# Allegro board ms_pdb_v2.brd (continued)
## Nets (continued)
UART_CTS_P1_L_N: J19.8(LAN8) J26.B65(GND27)
UART_CTS_P2_L_N: J21.8(LAN8) J26.A65(HSIP11-)
UART_CTS_P5_L_N: J23.8(LAN8) J26.B57(GND23)
UART_CTS_P6_L_N: J26.A57(HSIP9-) J27.8(LAN8)
UART_DSR_P1_L_N: J19.2(LAN2) J26.B61(GND25)
UART_DSR_P2_L_N: J21.2(LAN2) J26.A61(HSIP10-)
UART_DSR_P5_L_N: J23.2(LAN2) J26.B53(GND21)
UART_DSR_P6_L_N: J26.A53(HSIP8-) J27.2(LAN2)
UART_DTR_P1_L_N: J19.7(LAN7) J26.B64(GND26)
UART_DTR_P2_L_N: J21.7(LAN7) J26.A64(HSIP11+)
UART_DTR_P5_L_N: J23.7(LAN7) J26.B56(GND22)
UART_DTR_P6_L_N: J26.A56(HSIP9+) J27.7(LAN7)
UART_RI_P5_L_N: J23.4(LAN4) J26.B58(HSOP10+)
UART_RI_P6_L_N: J26.A58(GND56) J27.4(LAN4)
UART_RTS_P1_L_N: J19.1(LAN1) J26.B60(GND24)
UART_RTS_P2_L_N: J21.1(LAN1) J26.A60(HSIP10+)
UART_RTS_P5_L_N: J23.1(LAN1) J26.B52(GND20)
UART_RTS_P6_L_N: J26.A52(HSIP8+) J27.1(LAN1)
UART_RX_P1_L: J19.3(LAN3) J26.B62(HSOP11+)
UART_RX_P2_L: J21.3(LAN3) J26.A62(GND58)
UART_RX_P5_L: J23.3(LAN3) J26.B54(HSOP9+)
UART_RX_P6_L: J26.A54(GND54) J27.3(LAN3)
UART_TX_P1_L: J19.6(LAN6) J26.B63(HSOP11-)
UART_TX_P2_L: J21.6(LAN6) J26.A63(GND59)
UART_TX_P5_L: J23.6(LAN6) J26.B55(HSOP9-)
UART_TX_P6_L: J26.A55(GND55) J27.6(LAN6)
N42126673: J29.10(D2) R148.1
N42126764: J29.9(D1) R149.1
N42130542: J29.12(D4) R150.2
N42132358: J28.12(D4) R153.2
N42132545: J28.10(D2) R151.1
N42132933: J28.9(D1) R152.1
N42241895: R154.2 U2.1(EN)
N42242090: R156.2 R157.1 U2.4(ADJ)
N42242336: C88.1 R155.2
N42263600: C92.1 R158.2 R159.1 R161.1 U3.1(C)
N42264085: R159.2 R160.1 U3.8(REF)

Pads without a net: J1 34; J2 34; J3 34; J4 34; J5 34; J6 34; J25 A13 A14 A16 A19 A21 A22 B14 B15 B17 B19 B20 B23 B24; J26 A67 A68 A69 B67 B70; J28 11; J29 11; NOREF#21 1; NOREF#35 1; NOREF#102 1; NOREF#108 1; NOREF#109 1; NOREF#110 1; U3 4 5

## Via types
v1: diameter 0.762, hole 0.381, TOP to BOTTOM, 31 vias
v2: diameter 0.508, hole 0.254, TOP to BOTTOM, 1901 vias
v3: diameter 0.66, hole 0.33, TOP to BOTTOM, 24 vias

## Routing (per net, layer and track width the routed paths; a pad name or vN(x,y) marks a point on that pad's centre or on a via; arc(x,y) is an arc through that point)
GND: length 352.2
  TOP w0.457: R7.2 v2(25.91,108.23) ; R50.1 v2(27.45,9.88) ; R39.1 v2(13.85,329.31) ; R65.2 R45.2 26.88,5.61 v2(27.01,5.74) ; R6.2 v2(25.72,196.62) ; v2(26.07,12.56) 26.65,11.98 R49.1 ; v2(68.6,206.3) 68.59,206.29 R120.2 ; R53.1 v2(24.76,367.77) ; R38.1 v2(16.02,329.26) ; R140.2 v2(14.59,318.36) ; R54.1 v2(25.22,454.65) ; R22.2 v2(26.84,461.07) ; R52.1 v2(25.06,278.49) ; R37.1 v2(17.16,329.35) ; R116.2 v2(69.85,117.63) ; R51.1 v2(24.92,189.27) ; R112.2 v2(67.98,29.35)
  TOP w0.508: C8.2 v2(68.97,66.13) ; C80.2 v2(82.5,509.34) ; C41.2 v2(68.25,215.26) ; C2.2 v2(76.12,20.01) ; R160.2 v2(22.52,178.84) ; C54.2 v2(69.11,302.71) ; C74.2 v2(73.53,437.83) ; C75.2 v2(72.28,437.76) ; R24.2 41.43,370.1 v2(41.43,370.1) ; R43.2 v2(24.74,8.34) ; C53.2 v2(70.31,302.71) ; v2(20.2,173.34) 19.76,172.9 U3.3 ; C56.2 v2(66.69,302.71) ; C73.2 v2(74.05,464.78) ; C47.2 v2(73.69,258.11) ; C17.2 v2(73.91,109.94) ; U3.2 v2(20.2,174.17) ; C9.2 v2(70.26,65.13) ; R69.2 v2(24.75,94.46) ; C26.2 v2(69.44,126.32) ; C27.2 v2(68.31,126.32) ; R124.2 v2(82.75,295.22) ; C33.2 v2(70.85,170.74) ; C10.2 v2(71.42,65.18) ; C44.2 v2(73.2,287.31) ; R63.2 v2(24.74,9.51) ; C62.2 v2(69.86,349.18) ; C46.2 v2(74.83,258.11) ; R71.2 v2(24.75,187.95) ; R27.2 v2(41.28,371.51) ; R47.2 v2(24.77,95.65) ; R48.2 v2(24.77,186.75) ; v2(41.47,461.17) 41.47,461.18 R23.2 ; R99.2 v2(46.83,254.4) ; C91.2 v2(22.56,449.86) ; C76.2 v2(71.04,437.74) ; v2(40.99,103.52) R11.2 ; C84.2 v2(69.55,482.18) ; C64.2 v2(72.16,421.61) ; R20.2 v2(26.84,285.98) ; R25.2 v2(41.18,281.14) ; C42.2 v2(67.1,215.23) ; C29.2 v2(69.37,199.64) ; C5.2 v2(79.52,20.01) ; R12.2 v2(41.3,17.31) ; U1.4 v2(13.75,333.7) ; C63.2 v2(68.73,349.16) ; C61.2 v2(71,349.13) ; C32.2 v2(71.97,170.74) ; C51.2 v2(73.46,331.63) ; C66.2 v2(74.7,420.77) ; C1.2 v2(74.8,21.01) ; R85.2 v2(25.17,448.49) ; C40.2 v2(69.42,215.2) ; C50.2 v2(72.09,332.48) ; R95.2 v2(46.9,249.79) ; R132.2 v2(74.58,472.1) ; U2.8 v2(17.88,456.28) ; R58.2 v2(24.64,366.71) ; C57.2 v2(68.64,376.62) ; R44.1 40.79,374.15 v2(41.21,373.73) ; R91.2 v2(46.79,245.71) ; R77.2 v2(24.61,271.15) ; C78.2 v2(79.9,510.31) ; C65.2 v2(73.51,420.77) ; C55.2 v2(67.87,302.71) ; R151.2 v2(2.83,416.16) ; U2.6 v2(20.42,456.23) ; C16.2 v2(72.81,109.94) ; C14.2 v2(66.82,37.51) ; C86.2 v2(13.99,447.8) ; C69.2 v2(75.1,391.98) ; C13.2 v2(67.92,37.48) ; C35.2 v2(68.61,170.74) ; C60.2 v2(72.2,349.13) ; R107.2 v2(46.77,258.9) ; C34.2 v2(69.73,170.74) ; C23.2 v2(73.91,154.23) ; C37.2 v2(73.96,242.94) ; C22.2 v2(72.48,155.08) ; C49.2 v2(71.41,258.11) ; R89.2 v2(46.81,240.88) ; C36.2 v2(72.64,243.78) ; R59.2 v2(24.85,360.55) ; C6.2 v2(80.66,20.01) ; R57.2 v2(24.58,272.35) ; U3.6 v2(21.89,172.9) ; v2(40.96,106.9) R8.2 ; R152.2 v2(4.2,416.05) ; C83.2 v2(70.68,482.18) ; C58.2 v2(69.98,375.78) ; C4.2 v2(78.4,20.01) ; C92.2 v2(20.72,179.18) ; C38.2 v2(75.15,242.94) ; R150.1 v2(3.41,125.97) ; R148.2 v2(2.77,147.03) ; C70.2 v2(73.93,391.98) ; R19.2 26.79,373.45 v2(26.79,374.12) ; C82.2 v2(71.81,482.18) ; v2(26.45,20.97) 26.45,19.86 R5.2 ; C7.2 v2(81.79,20.01) ; C68.2 v2(76.3,391.98) ; R42.1 40.47,197.27 v2(40.93,196.82) ; R55.2 v2(25.04,183.07) ; R61.2 v2(25.16,447.25) ; R128.2 v2(79.73,384.53) ; C59.2 v2(71.12,375.78) ; R46.2 v2(24.89,99.37) ; R60.2 v2(25.16,453.54) ; v2(41.18,459.17) R26.2 ; C87.2 v2(14.11,449.79) ; C88.2 v2(23.82,444.05) ; C15.2 v2(71.52,110.79) ; R73.2 v2(25.04,181.85) ; R81.2 v2(24.74,361.78) ; C12.2 v2(69.07,37.5) ; C18.2 v2(74.8,81.96) ; C48.2 v2(72.56,258.11) ; v2(23.23,448.33) 23.07,448.33 22.85,448.1 C89.2 22.11,447.41 22.51,447.01 R157.2 ; R153.1 v2(2.93,396.83) ; v2(41.79,283.5) R21.2 ; C20.2 v2(72.52,81.96) ; R79.2 v2(24.64,365.5) ; C71.2 v2(71.39,465.98) ; U3.7 v2(22.01,174.17) ; C30.2 v2(70.66,198.79) ; C67.2 v2(77.44,391.98) ; R103.2 46.78,260.36 v2(47.85,259.29) ; C19.2 v2(73.63,81.96) ; C24.2 v2(75.06,154.23) ; U2.5 v2(21.69,456.24) ; R67.2 v2(24.8,100.59) ; C45.2 v2(74.35,287.31) ; C11.2 v2(70.24,37.49) ; U2.7 v2(19.15,456.24) ; v2(41.25,14.41) R9.2 ; C81.2 v2(72.93,482.18) ; R40.1 v2(41.08,18.41) ; C31.2 v2(71.82,198.79) ; C28.2 v2(67.19,126.32) ; C72.2 v2(72.8,464.67) ; R75.2 v2(24.63,276.12) ; C77.2 v2(69.77,437.69) ; R13.2 v2(41.06,194.11) ; C85.2 v2(13.96,445.81) ; R56.2 v2(24.62,277.38) ; C43.2 v2(71.87,288.16) ; R149.2 v2(4.06,147.03) ; C25.2 v2(70.56,126.32) ; v2(41.1,192.22) R10.2 ; C3.2 v2(77.25,20.01) ; C39.2 v2(70.56,215.2) ; C52.2 v2(74.71,331.63) ; C79.2 v2(81.29,509.32) ; C21.2 v2(71.39,81.96) ; C90.2 v2(14.33,451.71) ; R83.2 v2(25.11,452.26)
  IN2 w0.635: CE1.2 49.15,18.57 ; CE1.2 48.2,17.62 ; CE1.2 47.25,18.57 ; CE1.2 48.2,19.52 ; 47.25,107.12 CE5.2 ; CE5.2 48.2,108.07 ; CE5.2 48.2,106.17 ; CE5.2 49.15,107.12 ; 48.8,417.68 CE19.2 ; CE19.2 49.76,418.64 ; CE19.2 48.8,419.59 ; CE19.2 47.85,418.64 ; CE13.2 48.58,286.16 ; CE13.2 48.58,284.25 ; CE13.2 49.53,285.21 ; CE13.2 47.62,285.21 ; 47.7,463.1 CE22.2 ; CE22.2 49.6,463.1 ; CE22.2 48.65,462.15 ; CE22.2 48.65,464.05 ; 48.47,172.18 CE9.2 ; CE9.2 48.47,174.09 ; CE9.2 47.51,173.14 ; CE9.2 49.42,173.14 ; 47.17,374.44 CE17.2 ; CE17.2 48.12,373.48 ; CE17.2 48.12,375.39 ; CE17.2 49.08,374.44 ; CE16.2 48.4,351.72 ; CE16.2 48.4,349.81 ; CE16.2 47.45,350.77 ; CE16.2 49.35,350.77 ; 47.85,507.68 CE23.2 ; CE23.2 48.8,508.63 ; CE23.2 49.75,507.68 ; CE23.2 48.8,506.72 ; CE10.2 48.73,197.68 ; CE10.2 48.73,195.78 ; CE10.2 49.68,196.73 ; CE10.2 47.78,196.73 ; CE3.2 48.35,63.84 ; CE3.2 49.3,62.88 ; CE3.2 47.4,62.88 ; CE3.2 48.35,61.93 ; 48.67,216.53 CE11.2 ; CE11.2 47.71,217.49 ; CE11.2 48.67,218.44 ; CE11.2 49.62,217.49 ; CE2.2 49.29,38.62 ; CE2.2 48.33,39.57 ; CE2.2 47.38,38.62 ; CE2.2 48.33,37.67 ; CE4.2 49.42,84.27 ; CE4.2 47.51,84.27 ; CE4.2 48.47,85.23 ; CE4.2 48.47,83.32 ; CE20.2 49.62,439.76 ; CE20.2 48.67,440.72 ; CE20.2 48.67,438.81 ; CE20.2 47.72,439.76 ; 48.4,127.7 CE6.2 ; CE6.2 49.35,128.66 ; CE6.2 47.45,128.66 ; CE6.2 48.4,129.61 ; CE15.2 49.68,329.97 ; CE15.2 48.73,330.93 ; CE15.2 48.73,329.02 ; CE15.2 47.78,329.97 ; CE14.2 48.6,307.34 ; CE14.2 47.65,306.38 ; CE14.2 49.55,306.38 ; CE14.2 48.6,305.43 ; CE24.2 49.6,519.02 ; CE24.2 47.7,519.02 ; CE24.2 48.65,519.97 ; CE24.2 48.65,518.07 ; 48.53,394.6 CE18.2 ; CE18.2 48.53,396.5 ; CE18.2 49.49,395.55 ; CE18.2 47.58,395.55 ; 48.33,481.75 CE21.2 ; CE21.2 47.38,482.71 ; CE21.2 48.33,483.66 ; CE21.2 49.29,482.71 ; CE12.2 49.86,241.54 ; CE12.2 50.82,240.59 ; CE12.2 48.91,240.59 ; CE12.2 49.86,239.64 ; 48.04,151.93 CE8.2 ; CE8.2 49.95,151.93 ; CE8.2 48.99,152.88 ; CE8.2 48.99,150.97
  BOTTOM w0.356: v2(89.49,479.37) 89.4,479.28 U7.7 ; v2(94.89,343.55) 94.52,343.18 U6.7 ; v2(91.9,79.23) 91.36,78.69 U4.7 ; U5.7 v2(89.92,165.65)
  BOTTOM w0.66: 48.65,518.07 CE24.2 ; CE24.2 48.65,519.97 ; CE24.2 47.7,519.02 ; CE24.2 49.6,519.02 ; 48.47,83.32 CE4.2 ; CE4.2 48.47,85.23 ; CE4.2 49.42,84.27 ; CE4.2 47.51,84.27 ; 48.33,481.75 CE21.2 ; CE21.2 47.38,482.71 ; CE21.2 48.33,483.66 ; CE21.2 49.29,482.71 ; 48.65,462.15 CE22.2 ; CE22.2 48.65,464.05 ; CE22.2 49.6,463.1 ; CE22.2 47.7,463.1 ; CE5.2 48.2,108.07 ; CE5.2 48.2,106.17 ; CE5.2 49.15,107.12 ; CE5.2 47.25,107.12 ; 48.2,17.62 CE1.2 ; CE1.2 47.25,18.57 ; CE1.2 48.2,19.52 ; CE1.2 49.15,18.57 ; 48.91,240.59 CE12.2 ; CE12.2 50.82,240.59 ; CE12.2 49.86,241.54 ; CE12.2 49.86,239.64 ; CE18.2 49.49,395.55 ; CE18.2 48.53,394.6 ; CE18.2 48.53,396.5 ; CE18.2 47.58,395.55 ; CE15.2 48.73,330.93 ; CE15.2 47.78,329.97 ; CE15.2 49.68,329.97 ; CE15.2 48.73,329.02 ; 47.4,62.88 CE3.2 ; CE3.2 49.3,62.88 ; CE3.2 48.35,61.93 ; CE3.2 48.35,63.84 ; CE19.2 49.76,418.64 ; CE19.2 48.8,417.68 ; CE19.2 48.8,419.59 ; CE19.2 47.85,418.64 ; CE7.2 49.66,263.22 ; CE7.2 49.66,261.31 ; CE7.2 48.71,262.27 ; CE7.2 50.61,262.27 ; 47.51,173.14 CE9.2 ; CE9.2 49.42,173.14 ; CE9.2 48.47,172.18 ; CE9.2 48.47,174.09 ; CE6.2 48.4,129.61 ; CE6.2 47.45,128.66 ; CE6.2 49.35,128.66 ; CE6.2 48.4,127.7 ; CE23.2 48.8,508.63 ; CE23.2 47.85,507.68 ; CE23.2 48.8,506.72 ; CE23.2 49.75,507.68 ; CE8.2 48.99,152.88 ; CE8.2 48.99,150.97 ; CE8.2 48.04,151.93 ; CE8.2 49.95,151.93 ; 48.33,37.67 CE2.2 ; CE2.2 49.29,38.62 ; CE2.2 48.33,39.57 ; CE2.2 47.38,38.62 ; CE10.2 49.68,196.73 ; CE10.2 48.73,195.78 ; CE10.2 48.73,197.68 ; CE10.2 47.78,196.73 ; 48.12,373.48 CE17.2 ; CE17.2 47.17,374.44 ; CE17.2 48.12,375.39 ; CE17.2 49.08,374.44 ; 47.65,306.38 CE14.2 ; CE14.2 48.6,305.43 ; CE14.2 49.55,306.38 ; CE14.2 48.6,307.34 ; CE13.2 48.58,286.16 ; CE13.2 49.53,285.21 ; CE13.2 47.62,285.21 ; CE13.2 48.58,284.25 ; 47.72,439.76 CE20.2 ; CE20.2 48.67,438.81 ; CE20.2 48.67,440.72 ; CE20.2 49.62,439.76 ; CE16.2 49.35,350.77 ; CE16.2 47.45,350.77 ; CE16.2 48.4,349.81 ; CE16.2 48.4,351.72 ; 48.67,216.53 CE11.2 ; CE11.2 48.67,218.44 ; CE11.2 49.62,217.49 ; CE11.2 47.71,217.49
  vias: v2(0.76,520.71) v2(0.76,508.01) v2(0.76,495.31) v2(0.76,482.61) v2(0.76,469.91) v2(0.76,457.21) v2(0.76,444.51) v2(0.76,431.81) v2(0.76,419.11) v2(0.77,408.98) v2(0.76,405.03) v2(0.76,393.71) v2(0.76,381.01) v2(0.76,368.31) v2(0.76,355.61) v2(0.76,342.91) v2(0.76,330.21) v2(0.76,317.51) v2(0.76,304.81) v2(0.76,292.11) v2(0.76,279.41) v2(0.76,266.71) v2(0.76,254.01) v2(0.76,241.31) v2(0.76,228.61) v2(0.76,215.91) v2(0.76,203.21) v2(0.76,190.51) v2(0.76,177.81) v2(0.76,165.11) v2(0.76,152.41) v2(0.76,139.71) v2(0.76,127.01) v2(0.76,114.31) v2(0.76,101.61) v2(0.76,88.91) v2(0.76,76.21) v2(0.76,63.51) v2(0.76,50.81) v2(0.76,38.11) v2(0.76,25.41) v2(0.76,13.22) v2(6.41,4.76) v2(6.82,525.24) v2(15.72,169.17) v2(19.11,4.76) v2(19.52,525.24) v2(27.94,529.24) v2(31.81,0.76) v2(38.59,487.23) v2(38.59,485.32) v2(38.59,483.28) v2(38.59,481.39) v2(38.63,479.37) v2(38.63,477.7) v2(38.63,475.8) v2(38.63,473.96) v2(38.85,304.36) v2(38.89,302.35) v2(38.89,300.67) v2(38.89,298.77) v2(38.89,296.94) v2(39.1,394.06) v2(39.1,392.15) v2(39.1,390.11) v2(39.1,388.22) v2(39.14,386.21) v2(39.14,384.54) v2(39.14,382.64) v2(39.14,380.8) v2(39.35,487.23) v2(39.35,485.32) v2(39.35,483.28) v2(39.35,481.39) v2(39.39,479.37) v2(39.39,477.7) v2(39.39,475.8) v2(39.39,473.96) v2(39.44,220.4) v2(39.44,218.49) v2(39.44,216.45) v2(39.44,214.56) v2(39.48,212.55) v2(39.48,210.87) v2(39.48,208.97) v2(39.61,304.36) v2(39.66,302.35) v2(39.66,300.67) v2(39.66,298.77) v2(39.66,296.94) v2(39.69,130.54) v2(39.69,128.63) v2(39.69,126.59) v2(39.69,124.7) v2(39.73,122.69) v2(39.73,121.01) v2(39.73,119.11) v2(39.73,117.28) v2(39.86,394.06) v2(39.86,392.15) v2(39.86,390.11) v2(39.86,388.22) v2(39.91,386.21) v2(39.91,384.54) v2(39.91,382.64) v2(39.91,380.8) v2(40.2,220.4) v2(40.2,218.49) v2(40.2,216.45) v2(40.2,214.56) v2(40.24,212.55) v2(40.24,210.87) v2(40.24,208.97) v2(40.47,487.23) v2(40.47,485.32) v2(40.47,483.28) v2(40.47,481.39) v2(40.52,479.37) v2(40.52,477.7) v2(40.52,475.8) v2(40.52,473.96) v2(40.45,130.54) v2(40.45,128.63) v2(40.45,126.59) v2(40.45,124.7) v2(40.5,122.69) v2(40.5,121.01) v2(40.5,119.11) v2(40.5,117.28) v2(40.64,529.24) v2(40.74,304.36) v2(40.78,302.35) v2(40.78,300.67) v2(40.78,298.77) v2(40.78,296.94) v2(40.99,394.06) v2(40.99,392.15) v2(40.99,390.11) v2(40.99,388.22) v2(41.03,386.21) v2(41.03,384.54) v2(41.03,382.64) v2(41.03,380.8) v2(41.24,487.23) v2(41.24,485.32) v2(41.24,483.28) v2(41.24,481.39) v2(41.28,479.37) v2(41.28,477.7) v2(41.28,475.8) v2(41.28,473.96) v2(41.33,220.4) v2(41.33,218.49) v2(41.33,216.45) v2(41.33,214.56) v2(41.37,212.55) v2(41.37,210.87) v2(41.37,208.97) v2(41.5,304.36) v2(41.54,302.35) v2(41.54,300.67) v2(41.54,298.77) v2(41.54,296.94) v2(41.75,394.06) v2(41.75,392.15) v2(41.75,390.11) v2(41.75,388.22) v2(41.79,386.21) v2(41.79,384.54) v2(41.79,382.64) v2(41.79,380.8) v2(42.09,220.4) v2(42.09,218.49) v2(42.09,216.45) v2(42.09,214.56) v2(42.13,212.55) v2(42.13,210.87) v2(42.13,208.97) v2(42.25,41.56) v2(42.25,39.65) v2(42.25,37.61) v2(42.25,35.72) v2(42.29,33.71) v2(42.29,32.03) v2(42.29,30.13) v2(42.29,28.3) v2(42.72,487.23) v2(42.72,485.32) v2(42.72,483.28) v2(42.72,481.39) v2(42.76,479.37) v2(42.76,477.7) v2(42.76,475.8) v2(42.98,304.36) v2(43.02,302.35) v2(43.02,300.67) v2(43.02,298.77) v2(43.01,41.56) v2(43.01,39.65) v2(43.01,37.61) v2(43.01,35.72) v2(43.05,33.71) v2(43.05,32.03) v2(43.05,30.13) v2(43.05,28.3) v2(43.23,394.06) v2(43.23,392.15) v2(43.23,390.11) v2(43.23,388.22) v2(43.27,386.21) v2(43.27,384.54) v2(43.27,382.64) v2(43.48,487.23) v2(43.48,485.32) v2(43.48,483.28) v2(43.48,481.39) v2(43.52,479.37) v2(43.52,477.7) v2(43.52,475.8) v2(43.57,220.4) v2(43.57,218.49) v2(43.57,216.45) v2(43.57,214.56) v2(43.61,212.55) v2(43.61,210.87) v2(43.61,208.97) v2(43.74,304.36) v2(43.78,302.35) v2(43.78,300.67) v2(43.78,298.77) v2(43.99,394.06) v2(43.99,392.15) v2(43.99,390.11) v2(43.99,388.22) v2(44.03,386.21) v2(44.03,384.54) v2(44.03,382.64) v2(44.13,41.56) v2(44.13,39.65) v2(44.13,37.61) v2(44.13,35.72) v2(44.18,33.71) v2(44.18,32.03) v2(44.18,30.13) v2(44.18,28.3) v2(44.33,220.4) v2(44.33,218.49) v2(44.33,216.45) v2(44.33,214.56) v2(44.37,212.55) v2(44.37,210.87) v2(44.37,208.97) v2(44.41,79.71) v2(44.41,77.8) v2(44.41,75.76) v2(44.41,73.87) v2(44.46,71.85) v2(44.46,70.18) v2(44.46,68.28) v2(44.46,66.44) v2(44.51,0.76) v2(44.62,487.23) v2(44.62,485.32) v2(44.62,483.28) v2(44.62,481.39) v2(44.66,479.37) v2(44.66,477.7) v2(44.66,475.8) v2(44.88,304.36) v2(44.93,302.35) v2(44.93,300.67) v2(44.93,298.77) v2(44.9,41.56) v2(44.9,39.65) v2(44.9,37.61) v2(44.9,35.72) v2(44.94,33.71) v2(44.94,32.03) v2(44.94,30.13) v2(44.94,28.3) v2(45.13,394.06) v2(45.13,392.15) v2(45.13,390.11) v2(45.13,388.22) v2(45.18,386.21) v2(45.18,384.54) v2(45.18,382.64) v2(45.18,79.71) v2(45.18,77.8) v2(45.18,75.76) v2(45.18,73.87) v2(45.22,71.85) v2(45.22,70.18) v2(45.22,68.28) v2(45.22,66.44) v2(45.38,487.23) v2(45.38,485.32) v2(45.38,483.28) v2(45.38,481.39) v2(45.42,479.37) v2(45.42,477.7) v2(45.42,475.8) v2(45.47,220.4) v2(45.47,218.49) v2(45.47,216.45) v2(45.47,214.56) v2(45.51,212.55) v2(45.51,210.87) v2(45.51,208.97) v2(45.64,304.36) v2(45.69,302.35) v2(45.69,300.67) v2(45.69,298.77) v2(45.89,394.06) v2(45.89,392.15) v2(45.89,390.11) v2(45.89,388.22) v2(45.94,386.21) v2(45.94,384.54) v2(45.94,382.64) v2(46.23,220.4) v2(46.23,218.49) v2(46.23,216.45) v2(46.23,214.56) v2(46.28,212.55) v2(46.28,210.87) v2(46.28,208.97) v2(53.34,529.24) v2(55.62,435.71) v2(55.62,433.8) v2(55.62,431.76) v2(55.62,429.87) v2(55.66,427.85) v2(55.66,426.18) v2(55.66,424.28) v2(55.66,422.44) v2(56.38,435.71) v2(56.38,433.8) v2(56.38,431.76) v2(56.38,429.87) v2(56.42,427.85) v2(56.42,426.18) v2(56.42,424.28) v2(56.42,422.44) v2(57.03,73.66) v2(57.03,71.75) v2(57.03,69.71) v2(57.03,67.82) v2(57.08,65.8) v2(57.08,64.13) v2(57.08,62.23) v2(57.08,60.4) v2(57.21,0.76) v2(57.5,435.71) v2(57.5,433.8) v2(57.5,431.76) v2(57.5,429.87) v2(57.55,427.85) v2(57.55,426.18) v2(57.55,424.28) v2(57.55,422.44) v2(57.8,73.66) v2(57.8,71.75) v2(57.8,69.71) v2(57.8,67.82) v2(57.84,65.8) v2(57.84,64.13) v2(57.84,62.23) v2(57.84,60.4) v2(57.86,162.31) v2(57.86,160.4) v2(57.86,158.36) v2(57.86,156.47) v2(57.9,154.46) v2(57.9,152.78) v2(57.9,150.88) v2(57.97,308.69) v2(57.97,306.78) v2(57.97,304.73) v2(58.26,435.71) v2(58.26,433.8) v2(58.26,431.76) v2(58.26,429.87) v2(58.31,427.85) v2(58.31,426.18) v2(58.31,424.28) v2(58.31,422.44) v2(58.26,130.38) v2(58.26,128.47) v2(58.26,126.43) v2(58.26,124.54) v2(58.31,122.52) v2(58.31,120.85) v2(58.31,118.95) v2(58.31,117.12) v2(58.62,162.31) v2(58.62,160.4) v2(58.62,158.36) v2(58.62,156.47) v2(58.73,308.69) v2(58.73,306.78) v2(58.73,304.73) v2(58.72,255.19) v2(58.72,253.28) v2(58.72,251.23) v2(58.72,249.34) v2(58.66,154.46) v2(58.66,152.78) v2(58.66,150.88) v2(58.76,247.33) v2(58.76,245.66) v2(58.76,243.76) v2(58.76,241.92) v2(59.02,130.38) v2(59.02,128.47) v2(59.02,126.43) v2(59.02,124.54) v2(59.07,122.52) v2(59.07,120.85) v2(59.07,118.95) v2(59.07,117.12) v2(59.27,73.66) v2(59.27,71.75) v2(59.27,69.71) v2(59.27,67.82) v2(59.32,65.8) v2(59.32,64.13) v2(59.32,62.23) v2(59.48,255.19) v2(59.48,253.28) v2(59.48,251.23) v2(59.48,249.34) v2(59.52,247.33) v2(59.52,245.66) v2(59.52,243.76) v2(59.52,241.92) v2(59.74,435.71) v2(59.74,433.8) v2(59.74,431.76) v2(59.74,429.87) v2(59.75,162.31) v2(59.75,160.4) v2(59.75,158.36) v2(59.75,156.47) v2(59.79,427.85) v2(59.79,426.18) v2(59.79,424.28) v2(59.79,154.46) v2(59.79,152.78) v2(59.79,150.88) v2(59.86,308.69) v2(59.86,306.78) v2(59.86,304.73) v2(60.04,73.66) v2(60.04,71.75) v2(60.04,69.71) v2(60.04,67.82) v2(60.08,65.8) v2(60.08,64.13) v2(60.08,62.23) v2(60.4,25.91) v2(60.4,24) v2(60.4,21.96) v2(60.4,20.06) v2(60.44,18.05) v2(60.44,16.38) v2(60.44,14.48) v2(60.51,435.71) v2(60.51,433.8) v2(60.51,431.76) v2(60.51,429.87) v2(60.55,427.85) v2(60.55,426.18) v2(60.55,424.28) v2(60.51,162.31) v2(60.51,160.4) v2(60.51,158.36) v2(60.51,156.47) v2(60.5,130.38) v2(60.5,128.47) v2(60.5,126.43) v2(60.5,124.54) v2(60.55,122.52) v2(60.55,120.85) v2(60.55,118.95) v2(60.62,308.69) v2(60.62,306.78) v2(60.62,304.73) v2(60.6,255.19) v2(60.6,253.28) v2(60.6,251.23) v2(60.6,249.34) v2(60.65,247.33) v2(60.65,245.66) v2(60.65,243.76) v2(60.65,241.92) v2(60.55,154.46) v2(60.55,152.78) v2(60.55,150.88) v2(61.18,73.66) v2(61.18,71.75) v2(61.18,69.71) v2(61.18,67.82) v2(61.22,65.8) v2(61.22,64.13) v2(61.22,62.23) v2(61.16,25.91) v2(61.16,24) v2(61.16,21.96) v2(61.16,20.06) v2(61.2,18.05) v2(61.2,16.38) v2(61.2,14.48) v2(61.26,130.38) v2(61.26,128.47) v2(61.26,126.43) v2(61.26,124.54) v2(61.31,122.52) v2(61.31,120.85) v2(61.31,118.95) v2(61.37,255.19) v2(61.37,253.28) v2(61.37,251.23) v2(61.37,249.34) v2(61.41,247.33) v2(61.41,245.66) v2(61.41,243.76) v2(61.41,241.92) v2(61.65,435.71) v2(61.65,433.8) v2(61.65,431.76) v2(61.65,429.87) v2(61.69,427.85) v2(61.69,426.18) v2(61.69,424.28) v2(61.94,73.66) v2(61.94,71.75) v2(61.94,69.71) v2(61.94,67.82) v2(61.99,162.31) v2(61.99,160.4) v2(61.99,158.36) v2(61.99,156.47) v2(62.03,154.46) v2(62.03,152.78) v2(62.03,150.88) v2(61.98,65.8) v2(61.98,64.13) v2(61.98,62.23) v2(62.1,308.69) v2(62.1,306.78) v2(62.1,304.73) v2(62.3,25.91) v2(62.3,24) v2(62.3,21.96) v2(62.3,20.06) v2(62.34,18.05) v2(62.34,16.38) v2(62.34,14.48) v2(62.41,435.71) v2(62.41,433.8) v2(62.41,431.76) v2(62.41,429.87) v2(62.41,130.38) v2(62.41,128.47) v2(62.41,126.43) v2(62.41,124.54) v2(62.45,427.85) v2(62.45,426.18) v2(62.45,424.28) v2(62.45,122.52) v2(62.45,120.85) v2(62.45,118.95) v2(62.75,162.31) v2(62.75,160.4) v2(62.75,158.36) v2(62.75,156.47) v2(62.84,255.19) v2(62.84,253.28) v2(62.84,251.23) v2(62.84,249.34) v2(62.79,154.46) v2(62.79,152.78) v2(62.79,150.88) v2(62.86,308.69) v2(62.86,306.78) v2(62.86,304.73) v2(62.89,247.33) v2(62.89,245.66) v2(62.89,243.76) v2(63.06,25.91) v2(63.06,24) v2(63.06,21.96) v2(63.06,20.06) v2(63.11,18.05) v2(63.11,16.38) v2(63.11,14.48) v2(63.17,130.38) v2(63.17,128.47) v2(63.17,126.43) v2(63.17,124.54) v2(63.21,122.52) v2(63.21,120.85) v2(63.21,118.95) v2(63.61,255.19) v2(63.61,253.28) v2(63.61,251.23) v2(63.61,249.34) v2(63.65,247.33) v2(63.65,245.66) v2(63.65,243.76) v2(63.89,162.31) v2(63.89,160.4) v2(63.89,158.36) v2(63.89,156.47) v2(63.93,154.46) v2(63.93,152.78) v2(63.93,150.88) v2(64,308.69) v2(64,306.78) v2(64,304.73) v2(64.75,255.19) v2(64.75,253.28) v2(64.75,251.23) v2(64.75,249.34) v2(64.65,162.31) v2(64.65,160.4) v2(64.65,158.36) v2(64.65,156.47) v2(64.7,154.46) v2(64.7,152.78) v2(64.7,150.88) v2(64.76,308.69) v2(64.76,306.78) v2(64.76,304.73) v2(64.79,247.33) v2(64.79,245.66) v2(64.79,243.76) v2(65.51,255.19) v2(65.51,253.28) v2(65.51,251.23) v2(65.51,249.34) v2(65.55,247.33) v2(65.55,245.66) v2(65.55,243.76) v2(66.04,529.24) v2(67.17,158.58) v2(67.93,158.58) v2(69.91,0.76) v2(70.12,158.66) v2(70.88,158.66) v2(78.74,529.24) v2(82.61,0.76) v2(89.25,349.56) v2(89.25,347.41) v2(89.25,345.45) v2(89.25,343.08) v2(89.25,340.41) v2(89.25,337.74) v2(90.02,349.56) v2(90.02,347.41) v2(90.02,345.45) v2(90.02,343.08) v2(90.02,340.41) v2(90.02,337.74) v2(91.44,529.24) v2(92.24,349.56) v2(92.24,347.41) v2(92.24,345.45) v2(92.24,343.08) v2(92.24,340.41) v2(92.24,337.74) v2(93.01,349.56) v2(93.01,347.41) v2(93.01,345.45) v2(93.01,343.08) v2(93.01,340.41) v2(93.01,337.74) v2(95.31,0.76) v2(102.24,525.05) v2(102.24,512.35) v2(102.24,499.65) v2(102.24,486.95) v2(102.24,474.25) v2(102.24,461.55) v2(102.24,448.85) v2(102.24,436.15) v2(102.24,423.45) v2(102.24,410.75) v2(102.24,398.05) v2(102.24,385.35) v2(102.24,372.65) v2(102.24,359.95) v2(102.24,347.25) v2(102.24,334.55) v2(102.24,321.85) v2(102.24,309.15) v2(102.24,296.45) v2(102.24,283.75) v2(102.24,271.05) v2(102.24,258.35) v2(102.24,245.65) v2(102.24,232.95) v2(102.24,220.25) v2(102.24,207.55) v2(102.24,194.85) v2(102.24,182.15) v2(102.24,169.45) v2(102.24,156.75) v2(102.24,144.05) v2(102.24,131.35) v2(102.24,118.65) v2(102.24,105.95) v2(102.24,93.25) v2(102.24,80.55) v2(102.24,67.85) v2(102.24,55.15) v2(102.24,42.45) v2(102.24,29.75) v2(102.24,17.05) v2(102.24,4.35)
GND3: length 9.4
  IN1 w0.127: J25.B13 4.83,337.79 7.09,337.79 7.82,338.51 10.18,338.51 v2(11.93,336.76)
GND4: length 10.6
  IN1 w0.127: J25.B16 7.12,335.67 7.92,334.87 11.28,334.87 v2(11.93,334.22)
GND6: length 8.4
  IN1 w0.127: v2(11.52,330.12) 10.7,330.94 7.79,330.94 7.36,331.37 5.37,331.37 4.67,330.67 J25.B21
GND7: length 9.9
  IN1 w0.127: J25.B22 7.16,329.67 7.93,328.9 11.33,328.9 v2(11.5,328.73)
GND8: length 8.4
  IN1 w0.127: v2(11.58,324.72) 7.88,324.72 6.73,325.87 5.78,325.87 4.98,326.67 J25.B25
GND28: length 33
  BOTTOM w0.152: v2(15.05,170.37) 15.05,187.14 10.64,191.54 10.64,191.89 9.07,193.46 7.85,193.46 7.06,192.67 J26.B68
GND29: length 27.3
  BOTTOM w0.152: J26.B69 4.82,190.8 7.33,190.8 8.17,191.64 10.03,191.64 13.84,187.83 v2(13.84,172.67)
GND36: length 4.2
  IN1 w0.127: J25.A12 10.3,339.67 v2(11.93,338.03)
GND37: length 6
  IN1 w0.127: v2(11.93,335.49) 10.76,336.67 J25.A15
GND38: length 3.3
  IN1 w0.127: J25.A18 10.8,333.67 v2(11.5,332.97)
GND39: length 3
  IN1 w0.127: J25.A20 v2(11.49,331.67)
GND40: length 5.6
  IN1 w0.127: v2(11.49,327.42) 10.48,328.44 7.77,328.44 7.54,328.67 J25.A23
GND41: length 3.7
  IN1 w0.127: J25.A24 10.05,326.07 v2(11.53,326.07)
GND61: length 23.2
  BOTTOM w0.152: J26.A70 8.46,190.68 10.32,190.68 13.21,187.79 13.21,172.08 13.76,171.53 v2(14.51,171.53)
P3V3: length 44.3
  TOP w0.508: v2(11.93,339.3) 12.69,340.06 R41.1 ; v2(11.93,339.3) 10.79,339.3 10.2,338.71 8.19,338.71 7.17,337.69 3.3,337.69 1.95,339.04 J25.B12 ; v2(11.93,339.3) 12.68,338.55 v1(12.68,333.08) 12.13,332.53 12.13,330.31 12.36,330.08 R36.1 12.78,329.04 13.24,328.59 14.36,328.59 14.92,329.15 ; R35.1 14.92,329.15 ; 14.92,329.15 14.92,329.12 15.46,328.59 17.62,328.59 18.26,329.23 R34.1 19.02,330.06 20.66,331.69 v1(20.66,332.92) 20.66,337.93 19.95,338.63 U1.8
P3V3_BUF: length 539.6
  TOP w0.559: U2.3 v2(20.42,451)
  IN2 w1.016: v2(20.42,451) v2(20.42,450.11) v2(20.42,449.22) 25.07,444.56 41.55,444.56 42.58,445.59 81.04,445.59 84.07,448.62 84.07,453.48 85.7,455.11 95.43,455.11 97.74,457.43 97.74,480.32 v2(95.11,482.95)
  BOTTOM w0.356: 98.56,351.12 C95.1 98.42,349.82 U6.14 98.42,347.03 99.41,346.03 ; C94.1 94.33,170.92 93.82,171.43 U5.14 93.82,174.67 93.9,174.75 ; U4.14 95.26,83.3 95.59,82.96 96.3,82.96 96.7,83.36 96.7,83.9 R162.1 ; v2(95.11,482.95) 93.63,482.95 93.3,483.28 U7.14
  BOTTOM w0.508: 99.04,84.64 98.36,83.96 C93.1 97.82,83.95 R162.1 ; C96.1 95.19,483.04 v2(95.11,482.95) ; C94.1 95.47,169.7 96.2,168.96
  BOTTOM w1.016: 93.9,174.75 95.43,176.28 95.43,180.59 99.01,184.18 99.01,190.82 100.94,192.75 100.94,217.98 97.63,221.29 97.63,281.47 98.81,282.65 98.81,290.69 93.04,296.46 93.04,307.45 99.04,313.44 99.04,339.95 99.41,340.33 99.41,346.03 ; 98.56,351.12 98.56,469.5 94.5,473.55 94.5,480.95 95.11,481.55 v2(95.11,482.95) ; 99.04,84.64 99.04,86.13 98.21,86.97 98.21,166.95 96.2,168.96
P12V: length 187.8
  TOP w0.457: R131.2 v2(74.32,473.6) ; R123.2 v2(82.14,297.89) ; R3.2 v2(41.03,110.77) ; R17.2 v2(41.11,464.37) ; R1.2 v2(40.98,22.38) ; R2.2 v2(41.02,199.17)
  TOP w0.559: 19.15,450.73 U2.2
  TOP w0.66: 52.23,195.78 CE10.1 ; CE10.1 51.28,196.73 ; CE10.1 53.18,196.73 ; CE10.1 52.23,197.68 ; CE14.1 52.1,307.34 ; CE14.1 53.05,306.38 ; CE14.1 52.1,305.43 ; CE14.1 51.15,306.38 ; CE16.1 51.9,351.72 ; CE16.1 50.95,350.77 ; CE16.1 51.9,349.81 ; CE16.1 52.85,350.77 ; 51.9,127.7 CE6.1 ; CE6.1 52.85,128.66 ; CE6.1 50.95,128.66 ; CE6.1 51.9,129.61 ; CE13.1 53.03,285.21 ; CE13.1 51.12,285.21 ; CE13.1 52.08,286.16 ; CE13.1 52.08,284.25 ; CE3.1 52.8,62.88 ; CE3.1 51.85,63.84 ; CE3.1 50.9,62.88 ; CE3.1 51.85,61.93 ; 51.97,83.32 CE4.1 ; CE4.1 51.97,85.23 ; CE4.1 51.01,84.27 ; CE4.1 52.92,84.27 ; 50.88,482.71 CE21.1 ; CE21.1 51.83,483.66 ; CE21.1 52.79,482.71 ; CE21.1 51.83,481.75 ; 51.22,439.76 CE20.1 ; CE20.1 52.17,440.72 ; CE20.1 52.17,438.81 ; CE20.1 53.12,439.76 ; 50.75,18.57 CE1.1 ; CE1.1 52.65,18.57 ; CE1.1 51.7,19.52 ; CE1.1 51.7,17.62 ; 52.15,462.15 CE22.1 ; CE22.1 53.1,463.1 ; CE22.1 52.15,464.05 ; CE22.1 51.2,463.1 ; 52.03,394.6 CE18.1 ; CE18.1 52.03,396.5 ; CE18.1 51.08,395.55 ; CE18.1 52.99,395.55 ; CE11.1 53.12,217.49 ; CE11.1 52.17,218.44 ; CE11.1 51.22,217.49 ; CE11.1 52.17,216.53 ; CE24.1 53.1,519.02 ; CE24.1 51.2,519.02 ; CE24.1 52.15,519.97 ; CE24.1 52.15,518.07 ; 51.35,418.64 CE19.1 ; CE19.1 52.3,419.59 ; CE19.1 52.3,417.68 ; CE19.1 53.26,418.64 ; CE12.1 53.36,241.54 ; CE12.1 53.36,239.64 ; CE12.1 52.41,240.59 ; CE12.1 54.32,240.59 ; CE7.1 54.11,262.27 ; CE7.1 53.16,263.22 ; CE7.1 52.21,262.27 ; CE7.1 53.16,261.31 ; CE5.1 52.65,107.12 ; CE5.1 51.7,108.07 ; CE5.1 51.7,106.17 ; CE5.1 50.75,107.12 ; 51.28,329.97 CE15.1 ; CE15.1 53.18,329.97 ; CE15.1 52.23,329.02 ; CE15.1 52.23,330.93 ; CE9.1 52.92,173.14 ; CE9.1 51.97,172.18 ; CE9.1 51.01,173.14 ; CE9.1 51.97,174.09 ; 51.54,151.93 CE8.1 ; CE8.1 52.49,152.88 ; CE8.1 53.45,151.93 ; CE8.1 52.49,150.97 ; CE17.1 52.58,374.44 ; CE17.1 51.62,375.39 ; CE17.1 50.67,374.44 ; CE17.1 51.62,373.48 ; CE23.1 52.3,508.63 ; CE23.1 52.3,506.72 ; CE23.1 51.35,507.68 ; CE23.1 53.25,507.68 ; 50.88,38.62 CE2.1 ; CE2.1 52.79,38.62 ; CE2.1 51.83,37.67 ; CE2.1 51.83,39.57
  TOP w1.016: C87.1 18.21,449.79 19.15,450.73
  IN1 w0.635: CE5.1 52.65,107.12 ; CE5.1 51.7,108.07 ; CE5.1 51.7,106.17 ; CE5.1 50.75,107.12 ; 51.9,349.81 CE16.1 ; CE16.1 50.95,350.77 ; CE16.1 51.9,351.72 ; CE16.1 52.85,350.77 ; CE18.1 52.03,396.5 ; CE18.1 51.08,395.55 ; CE18.1 52.03,394.6 ; CE18.1 52.99,395.55 ; CE1.1 51.7,19.52 ; CE1.1 52.65,18.57 ; CE1.1 51.7,17.62 ; CE1.1 50.75,18.57 ; CE24.1 52.15,519.97 ; CE24.1 52.15,518.07 ; CE24.1 51.2,519.02 ; CE24.1 53.1,519.02 ; CE14.1 53.05,306.38 ; CE14.1 52.1,305.43 ; CE14.1 52.1,307.34 ; CE14.1 51.15,306.38 ; CE8.1 53.45,151.93 ; CE8.1 51.54,151.93 ; CE8.1 52.49,152.88 ; CE8.1 52.49,150.97 ; 52.41,240.59 CE12.1 ; CE12.1 53.36,241.54 ; CE12.1 54.32,240.59 ; CE12.1 53.36,239.64 ; 52.3,417.68 CE19.1 ; CE19.1 53.26,418.64 ; CE19.1 51.35,418.64 ; CE19.1 52.3,419.59 ; CE21.1 51.83,483.66 ; CE21.1 50.88,482.71 ; CE21.1 51.83,481.75 ; CE21.1 52.79,482.71 ; CE3.1 52.8,62.88 ; CE3.1 51.85,63.84 ; CE3.1 50.9,62.88 ; CE3.1 51.85,61.93 ; CE20.1 53.12,439.76 ; CE20.1 52.17,440.72 ; CE20.1 51.22,439.76 ; CE20.1 52.17,438.81 ; 50.88,38.62 CE2.1 ; CE2.1 51.83,39.57 ; CE2.1 51.83,37.67 ; CE2.1 52.79,38.62 ; 50.67,374.44 CE17.1 ; CE17.1 51.62,373.48 ; CE17.1 51.62,375.39 ; CE17.1 52.58,374.44 ; CE22.1 53.1,463.1 ; CE22.1 51.2,463.1 ; CE22.1 52.15,462.15 ; CE22.1 52.15,464.05 ; CE13.1 53.03,285.21 ; CE13.1 52.08,286.16 ; CE13.1 52.08,284.25 ; CE13.1 51.12,285.21 ; CE23.1 52.3,508.63 ; CE23.1 51.35,507.68 ; CE23.1 52.3,506.72 ; CE23.1 53.25,507.68 ; 51.97,172.18 CE9.1 ; CE9.1 52.92,173.14 ; CE9.1 51.97,174.09 ; CE9.1 51.01,173.14 ; 51.28,329.97 CE15.1 ; CE15.1 53.18,329.97 ; CE15.1 52.23,330.93 ; CE15.1 52.23,329.02 ; 51.97,83.32 CE4.1 ; CE4.1 51.97,85.23 ; CE4.1 52.92,84.27 ; CE4.1 51.01,84.27 ; 52.23,195.78 CE10.1 ; CE10.1 52.23,197.68 ; CE10.1 51.28,196.73 ; CE10.1 53.18,196.73 ; CE11.1 52.17,218.44 ; CE11.1 53.12,217.49 ; CE11.1 51.22,217.49 ; CE11.1 52.17,216.53 ; 51.9,127.7 CE6.1 ; CE6.1 50.95,128.66 ; CE6.1 52.85,128.66 ; CE6.1 51.9,129.61
  vias: v2(14.82,325.07) v2(14.84,323.19) v2(15.02,319.44) v2(39.56,343.98) v2(39.56,341.84) v2(39.56,339.87) v2(39.56,337.5) v2(39.56,334.83) v2(39.56,332.16) v2(39.95,164.99) v2(39.95,162.85) v2(39.95,160.89) v2(39.95,158.52) v2(39.95,155.85) v2(39.95,153.61) v2(40.26,432.76) v2(40.26,430.61) v2(40.26,428.65) v2(40.26,426.28) v2(40.26,423.61) v2(40.26,420.94) v2(40.32,343.98) v2(40.32,341.84) v2(40.32,339.87) v2(40.32,337.5) v2(40.32,334.83) v2(40.32,332.16) v2(40.71,164.99) v2(40.71,162.85) v2(40.71,160.89) v2(40.71,158.52) v2(40.71,155.85) v2(40.71,153.61) v2(41.02,432.76) v2(41.02,430.61) v2(41.02,428.65) v2(41.02,426.28) v2(41.02,423.61) v2(41.02,420.94) v2(41.51,259.01) v2(41.51,256.87) v2(41.51,254.91) v2(41.58,252.46) v2(41.58,249.79) v2(41.58,247.12) v2(42.16,79.33) v2(42.16,77.18) v2(42.16,75.22) v2(42.16,72.85) v2(42.16,70.18) v2(42.16,67.51) v2(42.27,259.01) v2(42.27,256.87) v2(42.27,254.91) v2(42.34,252.46) v2(42.34,249.79) v2(42.34,247.12) v2(42.92,79.33) v2(42.92,77.18) v2(42.92,75.22) v2(42.92,72.85) v2(42.92,70.18) v2(42.92,67.51) v2(55.3,43.98) v2(55.3,43.21) v2(55.3,41.83) v2(55.3,41.07) v2(55.3,39.87) v2(55.3,39.11) v2(55.67,340.32) v2(55.67,338.41) v2(55.67,336.37) v2(55.67,334.48) v2(55.71,332.47) v2(55.68,330.7) v2(55.68,328.8) v2(55.68,326.97) v2(56.28,525.14) v2(56.28,523) v2(56.28,521.04) v2(56.28,518.66) v2(56.28,516) v2(56.28,513.33) v2(56.43,340.32) v2(56.43,338.41) v2(56.43,336.37) v2(56.43,334.48) v2(56.44,330.7) v2(56.44,328.8) v2(56.44,326.97) v2(56.48,332.47) v2(57.55,525.14) v2(57.55,523) v2(57.55,521.04) v2(57.55,518.66) v2(57.55,516) v2(57.55,513.33) v2(57.56,340.32) v2(57.56,338.41) v2(57.56,336.37) v2(57.56,334.48) v2(57.6,332.47) v2(57.57,330.7) v2(57.57,328.8) v2(57.57,326.97) v2(57.84,43.98) v2(57.84,43.21) v2(57.84,41.83) v2(57.84,41.07) v2(57.84,39.87) v2(57.84,39.11) v2(58.32,340.32) v2(58.32,338.41) v2(58.32,336.37) v2(58.32,334.48) v2(58.33,330.7) v2(58.33,328.8) v2(58.33,326.97) v2(58.36,332.47) v2(58.81,525.14) v2(58.81,523) v2(58.81,521.04) v2(58.81,518.66) v2(58.81,516) v2(58.81,513.33) v2(59.11,291.06) v2(59.11,288.4) v2(59.11,285.72) v2(59.44,195.82) v2(59.44,193.68) v2(59.44,191.71) v2(59.8,340.32) v2(59.8,338.41) v2(59.8,336.37) v2(59.8,334.48) v2(59.84,332.47) v2(59.81,330.7) v2(59.81,328.8) v2(59.87,291.06) v2(59.87,288.4) v2(59.87,285.72) v2(60.08,525.14) v2(60.08,523) v2(60.08,521.04) v2(60.08,518.66) v2(60.08,516) v2(60.08,513.33) v2(60.2,195.82) v2(60.2,193.68) v2(60.2,191.71) v2(60.56,340.32) v2(60.56,338.41) v2(60.56,336.37) v2(60.56,334.48) v2(60.6,332.47) v2(60.57,330.7) v2(60.57,328.8) v2(60.55,221.32) v2(60.55,219.17) v2(60.55,217.21) v2(60.64,43.98) v2(60.64,43.21) v2(60.64,41.83) v2(60.64,41.07) v2(60.64,39.87) v2(60.64,39.11) v2(60.9,106.91) v2(60.9,106.15) v2(60.9,104.24) v2(60.9,103.48) v2(60.9,101.57) v2(60.9,100.81) v2(61.31,221.32) v2(61.31,219.17) v2(61.31,217.21) v2(61.62,525.14) v2(61.62,523) v2(61.62,521.04) v2(61.62,518.66) v2(61.62,516) v2(61.62,513.33) v2(61.64,291.06) v2(61.64,288.4) v2(61.64,285.72) v2(61.7,340.32) v2(61.7,338.41) v2(61.7,336.37) v2(61.7,334.48) v2(61.75,332.47) v2(61.71,330.7) v2(61.71,328.8) v2(61.97,195.82) v2(61.97,193.68) v2(61.97,191.71) v2(62.4,291.06) v2(62.4,288.4) v2(62.4,285.72) v2(62.46,340.32) v2(62.46,338.41) v2(62.46,336.37) v2(62.46,334.48) v2(62.51,332.47) v2(62.47,330.7) v2(62.47,328.8) v2(62.73,195.82) v2(62.73,193.68) v2(62.73,191.71) v2(62.89,525.14) v2(62.89,523) v2(62.89,521.04) v2(62.89,518.66) v2(62.89,516) v2(62.89,513.33) v2(63.01,43.98) v2(63.01,43.21) v2(63.01,41.83) v2(63.01,41.07) v2(63.01,39.87) v2(63.01,39.11) v2(63.17,106.94) v2(63.17,106.18) v2(63.17,104.28) v2(63.17,103.51) v2(63.17,101.61) v2(63.17,100.84) v2(63.54,221.32) v2(63.54,219.17) v2(63.54,217.21) v2(63.57,467.38) v2(63.57,465.62) v2(63.57,463.86) v2(63.62,462.04) v2(63.62,460.28) v2(63.62,458.52) v2(63.87,437.42) v2(63.94,435.53) v2(63.94,433.57) v2(63.94,431.19) v2(63.94,428.53) v2(63.94,425.85) v2(63.86,291.03) v2(63.86,288.36) v2(63.86,285.69) v2(64.22,68.12) v2(64.22,65.98) v2(64.22,64.01) v2(64.22,61.64) v2(64.22,58.97) v2(64.22,56.3) v2(64.34,467.38) v2(64.34,465.62) v2(64.34,463.86) v2(64.31,221.32) v2(64.31,219.17) v2(64.31,217.21) v2(64.38,462.04) v2(64.38,460.28) v2(64.38,458.52) v2(64.63,437.42) v2(64.63,291.03) v2(64.63,288.36) v2(64.63,285.69) v2(64.7,435.53) v2(64.7,433.57) v2(64.7,431.19) v2(64.7,428.53) v2(64.7,425.85) v2(64.78,195.82) v2(64.78,193.68) v2(64.78,191.71) v2(64.86,525.14) v2(64.86,523) v2(64.86,521.04) v2(64.86,518.66) v2(64.86,516) v2(64.86,513.33) v2(64.98,68.12) v2(64.98,65.98) v2(64.98,64.01) v2(64.98,61.64) v2(64.98,58.97) v2(64.98,56.3) v2(65.17,335.01) v2(65.17,332.87) v2(65.17,330.91) v2(65.17,328.54) v2(65.17,325.87) v2(65.17,323.2) v2(65.24,43.98) v2(65.24,43.21) v2(65.24,41.83) v2(65.24,41.07) v2(65.24,39.87) v2(65.24,39.11) v2(65.17,17.39) v2(65.17,16.62) v2(65.17,14.72) v2(65.17,13.96) v2(65.17,12.34) v2(65.17,11.58) v2(65.42,106.85) v2(65.42,106.08) v2(65.42,104.18) v2(65.42,103.41) v2(65.42,101.51) v2(65.42,100.74) v2(65.54,195.82) v2(65.54,193.68) v2(65.54,191.71) v2(65.65,467.38) v2(65.65,465.62) v2(65.65,463.86) v2(65.69,462.04) v2(65.69,460.28) v2(65.69,458.52) v2(65.68,423.76) v2(65.68,421.62) v2(65.68,419.65) v2(65.68,417.28) v2(65.68,414.61) v2(65.68,411.94) v2(65.93,335.01) v2(65.93,332.87) v2(65.93,330.91) v2(65.93,328.54) v2(65.93,325.87) v2(65.93,323.2) v2(66.13,525.14) v2(66.13,523) v2(66.13,521.04) v2(66.13,518.66) v2(66.13,516) v2(66.13,513.33) v2(66.16,290.99) v2(66.16,288.32) v2(66.16,285.65) v2(66.28,393.19) v2(66.28,391.43) v2(66.28,389.67) v2(66.41,467.38) v2(66.41,465.62) v2(66.41,463.86) v2(66.44,423.76) v2(66.44,421.62) v2(66.44,419.65) v2(66.44,417.28) v2(66.44,414.61) v2(66.44,411.94) v2(66.45,68.12) v2(66.45,65.98) v2(66.45,64.01) v2(66.45,61.64) v2(66.45,58.97) v2(66.45,56.3) v2(66.46,462.04) v2(66.46,460.28) v2(66.46,458.52) v2(66.67,437.42) v2(66.74,435.53) v2(66.74,433.57) v2(66.74,431.19) v2(66.74,428.53) v2(66.74,425.85) v2(66.71,251.6) v2(66.71,249.46) v2(66.71,247.49) v2(66.74,245.64) v2(66.74,243.8) v2(66.74,241.13) v2(66.92,290.99) v2(66.92,288.32) v2(66.92,285.65) v2(67.04,393.19) v2(67.04,391.43) v2(67.04,389.67) v2(67.1,156.83) v2(67.1,154.69) v2(67.1,152.73) v2(67.1,150.35) v2(67.1,147.69) v2(67.1,145.45) v2(67.08,17.39) v2(67.08,16.62) v2(67.08,14.72) v2(67.08,13.96) v2(67.08,12.34) v2(67.08,11.58) v2(67.21,68.12) v2(67.21,65.98) v2(67.21,64.01) v2(67.21,61.64) v2(67.21,58.97) v2(67.21,56.3) v2(67.44,437.42) v2(67.5,435.53) v2(67.5,433.57) v2(67.5,431.19) v2(67.5,428.53) v2(67.5,425.85) v2(67.47,251.6) v2(67.47,249.46) v2(67.47,247.49) v2(67.5,245.64) v2(67.5,243.8) v2(67.5,241.13) v2(67.57,106.85) v2(67.57,106.08) v2(67.57,104.18) v2(67.57,103.42) v2(67.57,101.51) v2(67.57,100.74) v2(67.85,525.14) v2(67.85,523) v2(67.85,521.04) v2(67.85,518.66) v2(67.85,516) v2(67.85,513.33) v2(67.83,467.38) v2(67.83,465.62) v2(67.83,463.86) v2(67.92,462.05) v2(67.92,460.28) v2(67.92,458.52) v2(67.86,156.83) v2(67.86,154.69) v2(67.86,152.73) v2(67.86,150.35) v2(67.86,147.69) v2(67.86,145.45) v2(67.98,335.01) v2(67.98,332.87) v2(67.98,330.91) v2(67.98,328.54) v2(67.98,325.87) v2(67.98,323.2) v2(68.21,393.19) v2(68.21,391.43) v2(68.21,389.67) v2(68.53,290.95) v2(68.53,288.29) v2(68.53,285.62) v2(68.59,467.38) v2(68.59,465.62) v2(68.59,463.86) v2(68.68,462.05) v2(68.68,460.28) v2(68.68,458.52) v2(68.67,423.76) v2(68.67,421.62) v2(68.67,419.65) v2(68.67,417.28) v2(68.67,414.61) v2(68.67,411.94) v2(68.74,335.01) v2(68.74,332.87) v2(68.74,330.91) v2(68.74,328.54) v2(68.74,325.87) v2(68.74,323.2) v2(68.97,393.19) v2(68.97,391.43) v2(68.97,389.67) v2(68.98,17.39) v2(68.98,16.62) v2(68.98,14.72) v2(68.98,13.96) v2(68.98,12.34) v2(68.98,11.58) v2(69.12,525.14) v2(69.12,523) v2(69.12,521.04) v2(69.12,518.66) v2(69.12,516) v2(69.12,513.33) v2(69.3,290.95) v2(69.3,288.29) v2(69.3,285.62) v2(69.43,423.76) v2(69.43,421.62) v2(69.43,419.65) v2(69.43,417.28) v2(69.43,414.61) v2(69.43,411.94) v2(69.7,251.6) v2(69.7,249.46) v2(69.7,247.49) v2(69.73,245.64) v2(69.73,243.8) v2(69.73,241.13) v2(69.73,106.88) v2(69.73,106.12) v2(69.73,104.21) v2(69.73,103.45) v2(69.73,101.54) v2(69.73,100.78) v2(69.95,393.24) v2(69.95,391.47) v2(69.95,389.72) v2(70.09,156.83) v2(70.09,154.69) v2(70.09,152.73) v2(70.09,150.35) v2(70.09,147.69) v2(70.09,145.45) v2(70.46,251.6) v2(70.46,249.46) v2(70.46,247.49) v2(70.5,245.64) v2(70.5,243.8) v2(70.5,241.13) v2(70.71,393.24) v2(70.71,391.47) v2(70.71,389.72) v2(70.85,156.83) v2(70.85,154.69) v2(70.85,152.73) v2(70.85,150.35) v2(70.85,147.69) v2(70.85,145.45) v2(71.06,17.39) v2(71.06,16.62) v2(71.06,14.72) v2(71.06,13.96) v2(71.06,12.34) v2(71.06,11.58) v2(71.88,393.24) v2(71.88,391.47) v2(71.88,389.72) v2(72.18,304.96) v2(72.18,302.81) v2(72.18,300.85) v2(72.64,393.24) v2(72.64,391.47) v2(72.64,389.72) v2(72.94,304.96) v2(72.94,302.81) v2(72.94,300.85) v2(73.18,17.39) v2(73.18,16.62) v2(73.18,14.72) v2(73.18,13.96) v2(73.18,12.34) v2(73.18,11.58) v2(73.55,135.32) v2(73.55,133.18) v2(73.55,131.22) v2(74.35,379.47) v2(74.35,377.7) v2(74.35,375.95) v2(74.31,135.32) v2(74.31,133.18) v2(74.31,131.22) v2(74.36,488.72) v2(74.36,486.96) v2(74.36,485.2) v2(74.4,374.13) v2(74.4,372.36) v2(74.4,370.61) v2(74.35,304.92) v2(74.35,302.78) v2(74.35,300.82) v2(75.12,488.72) v2(75.12,486.96) v2(75.12,485.2) v2(75.11,379.47) v2(75.11,377.7) v2(75.11,375.95) v2(75.11,304.92) v2(75.11,302.78) v2(75.11,300.82) v2(75.16,374.13) v2(75.16,372.36) v2(75.16,370.61) v2(75.57,135.25) v2(75.57,133.11) v2(75.57,131.14) v2(76.29,488.72) v2(76.29,486.96) v2(76.29,485.2) v2(76.34,135.25) v2(76.34,133.11) v2(76.34,131.14) v2(76.43,379.47) v2(76.43,377.7) v2(76.43,375.95) v2(76.38,304.98) v2(76.38,302.83) v2(76.38,300.87) v2(76.47,374.13) v2(76.47,372.36) v2(76.47,370.61) v2(77.05,488.72) v2(77.05,486.96) v2(77.05,485.2) v2(77.14,304.98) v2(77.14,302.83) v2(77.14,300.87) v2(77.19,379.47) v2(77.19,377.7) v2(77.19,375.95) v2(77.23,374.13) v2(77.23,372.36) v2(77.23,370.61) v2(77.25,177.11) v2(77.25,174.96) v2(77.25,173) v2(77.25,170.63) v2(77.25,167.96) v2(77.25,165.72) v2(77.46,135.28) v2(77.46,133.13) v2(77.46,131.17) v2(78.03,488.77) v2(78.03,487) v2(78.03,485.24) v2(77.98,262.56) v2(78.01,260.88) v2(78.03,259.25) v2(78.01,257.58) v2(78,255.85) v2(78.05,254.33) v2(78.02,177.11) v2(78.02,174.96) v2(78.02,173) v2(78.02,170.63) v2(78.02,167.96) v2(78.02,165.72) v2(78.22,135.28) v2(78.22,133.13) v2(78.22,131.17) v2(78.53,304.98) v2(78.53,302.83) v2(78.53,300.87) v2(78.6,379.47) v2(78.6,377.7) v2(78.6,375.95) v2(78.7,374.13) v2(78.7,372.36) v2(78.7,370.61) v2(78.74,262.56) v2(78.79,488.77) v2(78.79,487) v2(78.79,485.24) v2(78.77,260.88) v2(78.79,259.25) v2(78.78,257.58) v2(78.76,255.85) v2(78.81,254.33) v2(79.29,304.98) v2(79.29,302.83) v2(79.29,300.87) v2(79.37,379.47) v2(79.37,377.7) v2(79.37,375.95) v2(79.46,374.13) v2(79.46,372.36) v2(79.46,370.61) v2(79.7,135.35) v2(79.7,133.21) v2(79.7,131.24) v2(79.96,488.77) v2(79.96,487) v2(79.96,485.24) v2(80.06,177.11) v2(80.06,174.96) v2(80.06,173) v2(80.06,170.63) v2(80.06,167.96) v2(80.06,165.72) v2(80.46,135.35) v2(80.46,133.21) v2(80.46,131.24) v2(80.72,488.77) v2(80.72,487) v2(80.72,485.24) v2(80.76,304.98) v2(80.76,302.83) v2(80.76,300.87) v2(80.78,262.56) v2(80.82,260.88) v2(80.83,259.25) v2(80.82,257.58) v2(80.8,255.85) v2(80.82,177.11) v2(80.82,174.96) v2(80.82,173) v2(80.82,170.63) v2(80.82,167.96) v2(80.82,165.72) v2(80.85,254.33) v2(81.52,304.98) v2(81.52,302.83) v2(81.52,300.87) v2(81.54,262.56) v2(81.58,260.88) v2(81.59,259.25) v2(81.58,257.58) v2(81.56,255.85) v2(81.61,254.33) v2(81.82,135.33) v2(81.82,133.19) v2(81.82,131.22) v2(82.59,135.33) v2(82.59,133.19) v2(82.59,131.22) v2(83.74,88.56) v2(83.74,79.24) v2(83.76,86.99) v2(83.76,85.16) v2(83.76,82.79) v2(83.76,80.93) v2(84.5,88.56) v2(84.52,86.99) v2(84.52,85.16) v2(84.52,82.79) v2(84.52,80.93) v2(84.5,79.24) v2(86.54,88.56) v2(86.55,79.24) v2(86.57,86.99) v2(86.57,85.16) v2(86.57,82.79) v2(86.57,80.93) v2(87.31,88.56) v2(87.33,86.99) v2(87.33,85.16) v2(87.33,82.79) v2(87.33,80.93) v2(87.31,79.24)
P12V_STBY: length 634.7
  TOP w0.457: v2(24.56,274.77) R74.2 R76.2
  TOP w0.508: 29.78,91.12 27.26,93.65 24.05,93.65 23.66,94.04 23.66,95.96 24.57,96.87 R68.2 R66.2 25.52,98.09 24.1,98.09 23.12,99.07 23.12,104.12 22.34,104.9 22.34,108.18 27.39,113.23 27.39,178.04 27.74,178.4 27.74,180.66 27.75,180.67 ; 29.78,91.12 28.73,90.08 28.73,22.09 29.66,21.17 34.18,21.17 35.51,19.83 J1.39 ; 29.78,91.12 32.06,91.12 33.27,92.33 33.27,107.38 34.11,108.23 J2.39 37.55,106.22 R4.2 ; 27.56,355.18 31.68,355.18 33.49,356.99 33.49,371.38 J5.39 ; 27.56,355.18 27.56,311.42 29.11,309.87 29.11,287.18 30.01,286.28 34.29,286.28 J4.39 ; 27.56,355.18 23.83,358.91 23.83,362.36 24.48,363.02 R80.2 R78.2 ; 27.75,180.67 29.03,180.67 30.06,179.64 35.96,179.64 37.38,181.06 37.38,186.91 41.92,191.44 41.92,195.17 41.51,195.57 39.71,195.57 39.4,195.88 R42.2 36.18,197.27 J3.39 ; 27.75,180.67 24.88,180.67 24.01,181.54 24.01,183.65 24.63,184.27 R72.2 R70.2 24.32,185.52 23.02,186.83 23.02,197.41 27.27,201.67 27.27,203.33 28.04,204.09 28.04,260.64 33.99,266.6 33.99,283.48 J4.39 ; J1.39 34.27,18.56 29.41,18.56 27.91,17.07 25.19,17.07 23.82,15.7 23.82,7.65 24.28,7.19 R62.2 25.6,6.17 R64.2 ; J1.39 36.96,18.41 R40.2 ; J4.39 37.07,283.5 R16.2 ; J5.39 36.26,374.15 R44.2 ; J5.39 32.61,376.36 32.61,378.53 31.33,379.82 29.66,379.82 28.77,380.7 28.77,441.94 24.4,446.31 24.4,448.9 25.21,449.71 R84.2 R82.2 24.76,450.98 23.83,451.91 23.83,456.59 26.18,458.94 28.42,458.94 29.32,458.04 31.75,458.04 J6.39 36.08,462.37 R18.2
  IN2 w0.457: J4.39 32.6,282.09 32.6,277.17 31.57,276.14 27.04,276.14 25.67,274.77 v2(24.56,274.77)
B1_PSU_ALERT_N: length 83.6
  BOTTOM w0.152: U4.2 94.61,76.71 v3(94.98,76.33) 94.98,76.13 94.39,75.54 94.39,73.26 97.62,70.04 97.62,35.74 84.76,22.89 84.76,16.38 82.85,14.47 82.85,11.94 84.07,10.72 88.55,10.72 89.45,9.82 J7.S4
B2_PSU_ALERT_N: length 86.6
  BOTTOM w0.152: J7.S9 89.45,6.3 88.55,7.21 88.55,7.91 89.03,8.4 89.03,9.73 88.4,10.36 83.92,10.36 82.49,11.8 82.49,14.62 84.4,16.53 84.4,23.04 97.26,35.89 97.26,69.89 94.03,73.12 94.03,75.9 v3(93.61,76.32) 93.61,76.76 93.31,77.07 U4.4
B3_PSU_ALERT_N: length 30.4
  BOTTOM w0.152: J8.S4 89.45,54.12 85.7,57.87 85.7,68.16 91.45,73.91 91.45,75.49 v3(92.01,76.04) 91.68,76.37 91.68,76.92 92.01,77.25 U4.6
B4_PSU_ALERT_N: length 39.3
  BOTTOM w0.152: U4.8 91.36,79.45 90.79,78.89 90.79,76.35 v3(90.64,76.19) 91.07,75.75 91.07,74.07 85.32,68.32 85.32,57.71 89.08,53.96 89.08,52.96 88.64,52.52 88.64,51.63 89.45,50.82 J8.S9
B5_PSU_ALERT_N: length 15.2
  BOTTOM w0.152: J9.S4 89.45,95.09 88.51,94.15 88.51,93.09 89.18,92.42 89.18,90.46 92.15,87.48 92.15,86.71 v3(91.58,86.13) 91.58,85.69 92.66,84.61 U4.10
B6_PSU_ALERT_N: length 12
  BOTTOM w0.152: U4.12 93.96,84.58 93.24,85.3 v3(93.24,86.39) 93.24,87.23 89.6,90.87 89.6,93.76 J9.S9
B7_PSU_ALERT_N: length 35.1
  BOTTOM w0.152: U5.2 93.17,166.04 92.55,165.42 v3(92.55,165.23) 91.18,163.86 89.28,163.86 85.37,159.95 85.37,153.82 82.51,150.96 82.51,147.95 87.5,142.96 88.76,142.96 89.45,142.27 J10.S4
B8_PSU_ALERT_N: length 36.3
  BOTTOM w0.152: U5.4 91.87,165.94 v3(91.16,165.23) 90.5,164.57 89.25,164.57 84.97,160.29 84.97,153.99 82.11,151.13 82.11,147.79 87.16,142.73 87.16,141.9 89.45,139.61 J10.S9
B9_PSU_ALERT_N: length 20
  BOTTOM w0.152: J11.S4 89.45,184.13 88.2,182.88 v3(88.2,176.3) 88.82,175.67 88.82,170.3 90.57,168.56 U5.6
B10_PSU_ALERT_N: length 10.6
  BOTTOM w0.152: U5.8 89.92,176.97 v3(89.5,177.38) 89.09,177.8 89.09,182.44 J11.S9
B11_PSU_ALERT_N: length 66.5
  BOTTOM w0.152: J12.S4 89.23,229.58 89.23,228.3 88.47,227.54 88.47,226.52 89.14,225.85 90.14,225.85 99.62,216.37 99.62,193.2 97.77,191.35 97.77,184.86 94.15,181.23 94.15,177.85 92.68,176.38 v3(92.08,176.38) 91.7,176 91.7,174.51 91.22,174.02 U5.10
B12_PSU_ALERT_N: length 62
  BOTTOM w0.152: J12.S9 90.39,226.31 90.39,226.1 99.98,216.52 99.98,193.05 98.13,191.2 98.13,184.71 94.57,181.15 94.57,177.37 v3(93.64,176.45) 93.64,175.96 92.52,174.83 U5.12
B13_PSU_ALERT_N: length 77.6
  BOTTOM w0.152: J13.S4 89.61,274.4 89.61,276.25 90.53,277.18 92.13,277.18 98,283.05 98,290.19 92.24,295.95 92.24,308.05 98.13,313.95 98.13,337.65 97.86,337.92 v3(97.86,339.01) 97.86,339.73 97.55,340.04 97.55,341.24 97.77,341.46 U6.2
B14_PSU_ALERT_N: length 81
  BOTTOM w0.152: U6.4 96.47,341.53 96.96,341.04 v3(96.96,340.56) 96.96,338.21 97.75,337.42 97.75,314.1 91.86,308.21 91.86,295.79 97.62,290.03 97.62,283.21 91.97,277.56 90.38,277.56 89.19,276.37 89.19,275.22 88.43,274.47 88.43,273.99 89.45,272.97 J13.S9
B15_PSU_ALERT_N: length 28.5
  BOTTOM w0.152: J14.S4 89.77,319.02 89.77,321.3 90.76,322.29 92.15,322.29 97.39,327.53 97.39,335.84 96.91,336.32 96.91,337.64 96.24,338.31 v3(96.24,338.8) 96.24,340.17 95.17,341.24 U6.6
B16_PSU_ALERT_N: length 38.2
  BOTTOM w0.152: J14.S9 89.45,317.35 88.42,318.39 88.42,318.94 89.35,319.87 89.35,321.4 90.6,322.66 92,322.66 97.02,327.68 97.02,335.69 96.53,336.17 96.53,337.49 95.68,338.34 95.68,339.74 v3(94.87,340.55) 93.96,341.45 93.96,346.51 94.52,347.07 U6.8
B17_PSU_ALERT_N: length 18.8
  BOTTOM w0.152: J15.S4 89.45,362.03 88.54,361.12 88.54,359.78 96.23,352.09 96.23,351.54 v3(96.01,351.32) 96.01,349.05 95.82,348.86 U6.10
B18_PSU_ALERT_N: length 15.9
  BOTTOM w0.152: J15.S9 89.27,360.42 89.27,359.6 96.62,352.25 v3(96.62,349.82) 96.62,349.43 97.12,348.93 U6.12
B19_PSU_ALERT_N: length 75.8
  BOTTOM w0.152: U7.2 92.65,475.39 v3(92.94,475.1) 92.94,473.8 97.41,469.33 97.41,417.52 89.34,409.45 89.34,407.7 J16.S4
B20_PSU_ALERT_N: length 79.2
  BOTTOM w0.152: U7.4 91.35,476.77 v3(91.7,476.42) 92.3,475.83 92.3,473.94 97.05,469.19 97.05,417.67 88.98,409.6 88.98,408.3 88.6,407.92 88.6,407.12 89.05,406.68 89.05,405.46 J16.S9
B21_PSU_ALERT_N: length 29.6
  BOTTOM w0.152: U7.6 90.05,477.01 89.73,476.68 v3(89.73,476.07) 89.73,475.66 85.43,471.36 85.43,458.47 89.45,454.45 J17.S4
B22_PSU_ALERT_N: length 38.4
  BOTTOM w0.152: J17.S9 89.45,450.93 88.55,451.83 88.55,452.57 89.08,453.1 89.08,454.23 85.07,458.24 85.07,471.51 88.16,474.6 v3(88.16,476.3) 88.72,476.86 88.72,480.81 89.4,481.49 U7.8
B23_PSU_ALERT_N: length 13.9
  BOTTOM w0.152: U7.10 90.7,485.35 v3(89.85,486.21) 89.85,492.41 88.49,493.76 88.49,494.37 89.45,495.33 J18.S4
B24_PSU_ALERT_N: length 11.1
  BOTTOM w0.152: J18.S9 90.24,493.17 90.24,486.98 v3(91.47,485.75) 92,485.22 U7.12
CM_PWR_CTL_IN: length 153.4
  TOP w0.152: J33.1 1.35,36.34 1.35,176.98 2.66,178.29 2.66,181.96 J26.B78
FAN1_TACH: length 170.6
  TOP w0.152: R142.1 12.75,325.38 9.42,325.38 8.96,324.91 7.72,324.91 7.17,325.47 4.75,325.47 J25.B27
  BOTTOM w0.152: J20.1 10.04,463.1 4.17,463.1 2.64,461.57 2.64,448.29 4.34,446.59 4.34,423.75 17.78,410.3 17.78,395.57 10.91,388.7 10.91,372.49 11.87,371.53 11.87,346.75 9.17,344.05 9.17,331.17 8.61,330.61 8.12,330.61 7.09,329.58 6.12,329.58 4.77,328.23 4.77,326.34 3.95,325.52 J25.B27
FAN2_TACH: length 159.5
  TOP w0.152: R143.1 10.82,321.89 9.76,322.95 7.99,322.95 7.26,323.67 J25.B28
  BOTTOM w0.152: J25.B28 4.17,323.67 6.3,321.54 7.1,321.54 7.79,320.86 9.16,320.86 10.33,322.03 10.33,324.79 10.96,325.42 10.96,342.7 13.65,345.39 13.65,371.9 23.66,381.91 23.66,408.9 13.39,419.17 13.39,447.15 J20.4
FAN3_TACH: length 141.3
  TOP w0.152: J25.B29 4.75,321.87 7.06,321.87 7.62,322.42 9.35,322.42 10.95,320.83 R144.1
  IN1 w0.127: J20.7 23.13,424.8 23.13,380.8 12.48,370.15 12.48,324.7 10.55,322.77 7.88,322.77 7.05,321.95 4.67,321.95 J25.B29
FAN4_TACH: length 114.2
  TOP w0.152: R145.1 12.47,326.71 10.31,326.71 9.75,326.15 8.93,326.15 J25.A26
  BOTTOM w0.152: J20.10 11.44,419.36 22.95,407.86 22.95,382.2 12.94,372.19 12.94,345.68 10.23,342.98 10.23,327.45 J25.A26
FAN5_TACH: length 159.2
  TOP w0.152: R146.1 10.91,324.01 10.39,324.53 7.4,324.53 7.26,324.67 J25.A27
  BOTTOM w0.152: J25.A27 7.58,325.8 7.58,326.24 8.13,326.8 8.75,326.8 9.88,327.93 9.88,343.13 12.58,345.83 12.58,372.34 22.59,382.35 22.59,407.39 8.51,421.47 8.51,444.67 4.29,448.89 4.29,460.04 J20.11
FAN6_TACH: length 145.4
  TOP w0.152: J25.A28 10.31,323.67 11.01,322.97 R147.1
  BOTTOM w0.152: J20.14 8.91,449.09 12.89,445.12 12.89,418.7 23.3,408.29 23.3,382.06 13.29,372.05 13.29,345.54 10.59,342.83 10.59,325.81 J25.A28
